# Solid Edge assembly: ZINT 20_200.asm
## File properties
Title: Zylinder
Author: bmolnar
Template: iso metric assembly.asm
Last saved by: bmolnar
Revision: 24
Application: Solid Edge
Username: bmolnar
Dokumentum tartalom típus: 1
Document Number: ZINT 20/200
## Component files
Kit_1.par
Kit_2.par
Profilrohr.par
Kolbenstange.par
Platte.par
hrungsstange.par
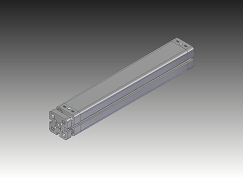
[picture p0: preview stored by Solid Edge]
